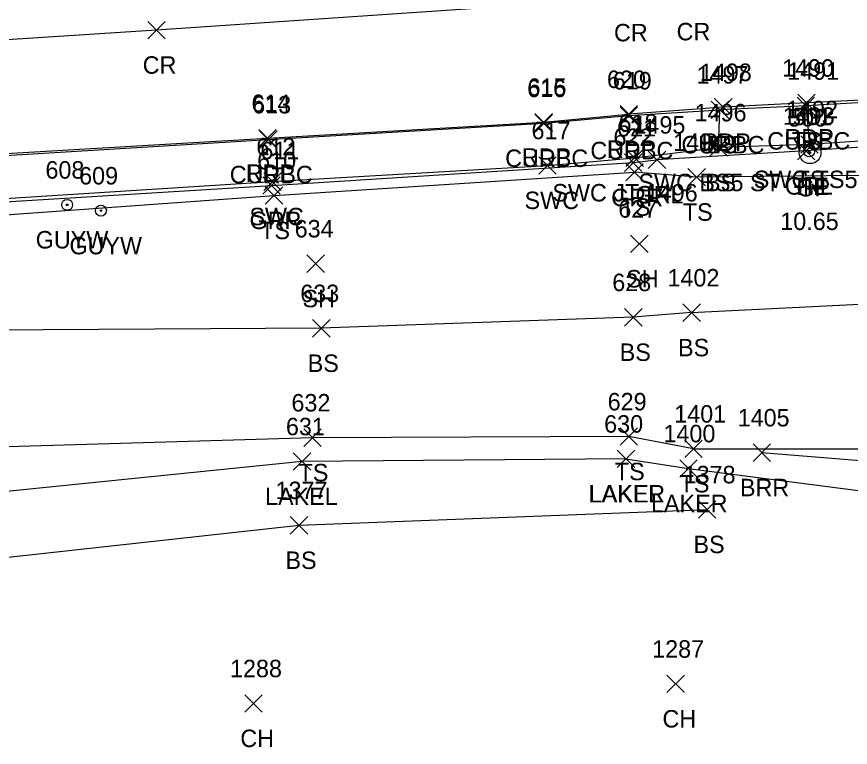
# Model space of a CAD drawing. Extents: x 1716490 to 1717645, y 888034 to 890004.
# Drawn here: x 1717358.9 to 1717454.4, y 888177 to 888260.7 of the extents above; entities that cross this region are included whole.
import ezdxf

# ---------------------------------------------------------------- set-up
doc = ezdxf.new("R2010")
doc.units = 0
for name, color, linetype in [('C_A', 7, 'Continuous'), ('C_C', 7, 'Continuous'), ('C_I', 7, 'Continuous'), ('CBP', 7, 'Continuous'), ('L_A', 7, 'Continuous'), ('L_I', 7, 'Continuous'), ('L_TIC', 7, 'Continuous'), ('LABL', 7, 'Continuous'), ('LAWE', 7, 'Continuous'), ('LELB', 7, 'Continuous'), ('P_A', 7, 'Continuous'), ('P_I', 7, 'Continuous'), ('P_TIC', 7, 'Continuous'), ('PET', 7, 'Continuous'), ('PRC', 7, 'Continuous'), ('R_A', 7, 'Continuous'), ('R_I', 7, 'Continuous'), ('R_TIC', 7, 'Continuous'), ('RC', 7, 'Continuous'), ('RGP', 7, 'Continuous'), ('RGR', 7, 'Continuous'), ('RSW', 7, 'Continuous'), ('U_A', 7, 'Continuous'), ('U_I', 7, 'Continuous'), ('UPGW', 7, 'Continuous')]:
    doc.layers.add(name, color=color, linetype=linetype)

msp = doc.modelspace()

# ---------------------------------------------------------------- linework, layer by layer
at = {"layer": 'CBP'}
for radius in [0.625, 0.0833]:
    msp.add_circle((1717449.723, 888245.268), radius, dxfattribs=at)
at = {"layer": 'L_TIC'}
for points in [[(1717448.343, 888249.478), (1717450.343, 888251.478)], [(1717450.343, 888249.478), (1717448.343, 888251.478)], [(1717438.503, 888249.043), (1717440.503, 888251.043)], [(1717440.503, 888249.043), (1717438.503, 888251.043)], [(1717438.35, 888244.712), (1717440.35, 888246.712)], [(1717440.35, 888244.712), (1717438.35, 888246.712)], [(1717448.774, 888245.071), (1717450.774, 888247.071)], [(1717450.774, 888245.071), (1717448.774, 888247.071)], [(1717428.711, 888241.895), (1717430.711, 888243.895)], [(1717430.711, 888241.895), (1717428.711, 888243.895)], [(1717435.838, 888241.33), (1717437.838, 888243.33)], [(1717437.838, 888241.33), (1717435.838, 888243.33)], [(1717387.412, 888239.225), (1717389.412, 888241.225)], [(1717389.412, 888239.225), (1717387.412, 888241.225)], [(1717429.269, 888233.684), (1717431.269, 888235.684)], [(1717431.269, 888233.684), (1717429.269, 888235.684)], [(1717392.184, 888231.418), (1717394.184, 888233.418)], [(1717394.184, 888231.418), (1717392.184, 888233.418)], [(1717435.262, 888225.802), (1717437.262, 888227.802)], [(1717437.262, 888225.802), (1717435.262, 888227.802)], [(1717428.575, 888225.271), (1717430.575, 888227.271)], [(1717430.575, 888225.271), (1717428.575, 888227.271)], [(1717392.828, 888224.01), (1717394.828, 888226.01)], [(1717394.828, 888224.01), (1717392.828, 888226.01)], [(1717391.814, 888211.48), (1717393.814, 888213.48)], [(1717393.814, 888211.48), (1717391.814, 888213.48)], [(1717428.056, 888211.605), (1717430.056, 888213.605)], [(1717430.056, 888211.605), (1717428.056, 888213.605)], [(1717435.472, 888210.206), (1717437.472, 888212.206)], [(1717437.472, 888210.206), (1717435.472, 888212.206)], [(1717443.304, 888209.768), (1717445.304, 888211.768)], [(1717445.304, 888209.768), (1717443.304, 888211.768)], [(1717390.617, 888208.758), (1717392.617, 888210.758)], [(1717392.617, 888208.758), (1717390.617, 888210.758)], [(1717427.732, 888209.055), (1717429.732, 888211.055)], [(1717429.732, 888209.055), (1717427.732, 888211.055)], [(1717427.732, 888209.055), (1717429.732, 888211.055)], [(1717429.732, 888209.055), (1717427.732, 888211.055)], [(1717434.889, 888207.946), (1717436.889, 888209.946)], [(1717436.889, 888207.946), (1717434.889, 888209.946)], [(1717434.889, 888207.946), (1717436.889, 888209.946)], [(1717436.889, 888207.946), (1717434.889, 888209.946)], [(1717437.033, 888203.252), (1717439.033, 888205.252)], [(1717439.033, 888203.252), (1717437.033, 888205.252)], [(1717390.277, 888201.442), (1717392.277, 888203.442)], [(1717392.277, 888201.442), (1717390.277, 888203.442)], [(1717433.429, 888183.275), (1717435.429, 888185.275)], [(1717435.429, 888183.275), (1717433.429, 888185.275)], [(1717385.06, 888181.038), (1717387.06, 888183.038)], [(1717387.06, 888181.038), (1717385.06, 888183.038)]]:
    msp.add_lwpolyline(points, dxfattribs=at)
at = {"layer": 'LABL'}
msp.add_lwpolyline([(1717444.304, 888210.768), (1717472.093, 888208.525), (1717508.027, 888209.443), (1717543.383, 888208.313), (1717559.79, 888208.697), (1717569.184, 888204.287)], dxfattribs=at)
at = {"layer": 'LAWE'}
for points in [[(1717428.732, 888210.055), (1717391.617, 888209.758), (1717351.712, 888205.712), (1717299.907, 888205.551), (1717265.677, 888204.481), (1717223.667, 888200.839), (1717208.555, 888201.757), (1717201.775, 888208.165), (1717191.379, 888215.041), (1717175.765, 888226.393)], [(1717428.732, 888210.055), (1717435.889, 888208.946)], [(1717435.889, 888208.946), (1717475.751, 888203.813), (1717512.343, 888207.141), (1717547.357, 888203.244), (1717562.879, 888195.852), (1717574.347, 888181.764)]]:
    msp.add_lwpolyline(points, dxfattribs=at)
at = {"layer": 'LELB'}
for points in [[(1717168.218, 888251.599), (1717169.763, 888223.631), (1717177.454, 888214.692), (1717194.469, 888204.087), (1717205.175, 888197.964), (1717222.801, 888195.904), (1717272.158, 888195.504), (1717301.802, 888198.153), (1717342.964, 888197.132), (1717391.277, 888202.442), (1717438.033, 888204.252)], [(1717449.343, 888250.478), (1717449.774, 888246.071)], [(1717439.35, 888245.712), (1717439.503, 888250.043)], [(1717558.191, 888231.225), (1717550.825, 888235.094), (1717537.711, 888239.81), (1717528.963, 888241.86), (1717509.305, 888244.845), (1717490.286, 888244.528), (1717470.299, 888242.67), (1717436.838, 888242.33)], [(1717195.004, 888228.651), (1717213.423, 888229.755), (1717254.51, 888232.617), (1717289.453, 888234.249), (1717344.856, 888237.074), (1717388.412, 888240.225), (1717429.711, 888242.895)], [(1717436.838, 888242.33), (1717429.711, 888242.895)], [(1717436.262, 888226.802), (1717464.721, 888228.238), (1717507.391, 888229.249), (1717536.749, 888229.804)], [(1717436.262, 888226.802), (1717429.575, 888226.271)], [(1717429.575, 888226.271), (1717393.828, 888225.01), (1717349.187, 888224.753), (1717340.986, 888224.942), (1717302.216, 888221.684), (1717265.436, 888218.579), (1717217.955, 888213.612)], [(1717436.472, 888211.206), (1717466.203, 888211.198), (1717507.829, 888212.694), (1717537.791, 888216.149), (1717563.771, 888215.069), (1717574.805, 888210.491), (1717582.49, 888199.54), (1717589.339, 888189.724)], [(1717429.056, 888212.605), (1717392.814, 888212.48), (1717352.659, 888211.275), (1717300.922, 888208.213), (1717265.266, 888207.117), (1717222.122, 888203.992)], [(1717436.472, 888211.206), (1717429.056, 888212.605)]]:
    msp.add_lwpolyline(points, dxfattribs=at)
at = {"layer": 'P_TIC'}
for points in [[(1717373.932, 888258.17), (1717375.932, 888260.17)], [(1717375.932, 888258.17), (1717373.932, 888260.17)], [(1717448.414, 888249.828), (1717450.414, 888251.828)], [(1717450.414, 888249.828), (1717448.414, 888251.828)], [(1717428.054, 888248.533), (1717430.054, 888250.533)], [(1717430.054, 888248.533), (1717428.054, 888250.533)], [(1717438.895, 888249.333), (1717440.895, 888251.333)], [(1717440.895, 888249.333), (1717438.895, 888251.333)], [(1717418.304, 888247.633), (1717420.304, 888249.633)], [(1717420.304, 888247.633), (1717418.304, 888249.633)], [(1717386.667, 888245.786), (1717388.667, 888247.786)], [(1717388.667, 888245.786), (1717386.667, 888247.786)]]:
    msp.add_lwpolyline(points, dxfattribs=at)
at = {"layer": 'PET'}
for points in [[(1717427.273, 888275.567), (1717374.238, 888271.922), (1717317.861, 888268.58), (1717269.995, 888265.537), (1717231.181, 888263.331), (1717177.059, 888260.693), (1717177.797, 888248.053), (1717178.6, 888236.513), (1717214.025, 888237.983), (1717254.522, 888239.738), (1717289.284, 888241.313), (1717339.424, 888243.96), (1717387.667, 888246.786), (1717419.304, 888248.633), (1717429.054, 888249.533)], [(1717594.517, 888190.334), (1717590.366, 888197.636), (1717582.375, 888209.703), (1717579.255, 888214.07), (1717576.4, 888218.115), (1717565.946, 888231.02), (1717560.234, 888236.413), (1717554.367, 888241.047), (1717546.423, 888245.577), (1717533.805, 888250.762), (1717523.466, 888253.269), (1717509.155, 888254.185), (1717488.825, 888253.07), (1717469.068, 888251.805), (1717449.414, 888250.828), (1717439.895, 888250.333)], [(1717439.895, 888250.333), (1717429.054, 888249.533)]]:
    msp.add_lwpolyline(points, dxfattribs=at)
at = {"layer": 'PRC'}
msp.add_lwpolyline([(1717428.93, 888262.876), (1717374.932, 888259.17), (1717318.782, 888255.519), (1717271.433, 888252.686), (1717231.272, 888251.088), (1717177.797, 888248.053)], dxfattribs=at)
at = {"layer": 'R_TIC'}
for points in [[(1717448.343, 888249.478), (1717450.343, 888251.478)], [(1717450.343, 888249.478), (1717448.343, 888251.478)], [(1717438.503, 888249.043), (1717440.503, 888251.043)], [(1717440.503, 888249.043), (1717438.503, 888251.043)], [(1717418.313, 888247.49), (1717420.313, 888249.49)], [(1717420.313, 888247.49), (1717418.313, 888249.49)], [(1717428.071, 888248.369), (1717430.071, 888250.369)], [(1717430.071, 888248.369), (1717428.071, 888250.369)], [(1717386.753, 888245.622), (1717388.753, 888247.622)], [(1717388.753, 888245.622), (1717386.753, 888247.622)], [(1717438.35, 888244.712), (1717440.35, 888246.712)], [(1717440.35, 888244.712), (1717438.35, 888246.712)], [(1717448.774, 888245.071), (1717450.774, 888247.071)], [(1717450.774, 888245.071), (1717448.774, 888247.071)], [(1717448.392, 888244.322), (1717450.392, 888246.322)], [(1717450.392, 888244.322), (1717448.392, 888246.322)], [(1717418.755, 888242.667), (1717420.755, 888244.667)], [(1717420.755, 888242.667), (1717418.755, 888244.667)], [(1717428.556, 888242.988), (1717430.556, 888244.988)], [(1717430.556, 888242.988), (1717428.556, 888244.988)], [(1717428.729, 888243.536), (1717430.729, 888245.536)], [(1717430.729, 888243.536), (1717428.729, 888245.536)], [(1717431.288, 888243.31), (1717433.288, 888245.31)], [(1717433.288, 888243.31), (1717431.288, 888245.31)], [(1717387.224, 888240.812), (1717389.224, 888242.812)], [(1717389.224, 888240.812), (1717387.224, 888242.812)], [(1717387.118, 888240.371), (1717389.118, 888242.371)], [(1717389.118, 888240.371), (1717387.118, 888242.371)]]:
    msp.add_lwpolyline(points, dxfattribs=at)
at = {"layer": 'RC'}
for points in [[(1717594.157, 888190.547), (1717590.511, 888197.229), (1717582.134, 888209.508), (1717579.157, 888213.908), (1717576.185, 888218.151), (1717565.853, 888230.61), (1717559.89, 888236.254), (1717554.327, 888240.707), (1717546.304, 888245.431), (1717533.609, 888250.562), (1717523.635, 888253.005), (1717509.034, 888253.878), (1717488.904, 888252.846), (1717469.137, 888251.622), (1717449.343, 888250.478), (1717439.503, 888250.043)], [(1717429.071, 888249.369), (1717439.503, 888250.043)], [(1717178.774, 888236.275), (1717214.142, 888237.798), (1717254.517, 888239.571), (1717289.15, 888241.078), (1717339.376, 888243.691), (1717387.753, 888246.622), (1717419.313, 888248.49), (1717429.071, 888249.369)]]:
    msp.add_lwpolyline(points, dxfattribs=at)
at = {"layer": 'RGP'}
msp.add_line((1717449.831, 888245.119), (1717449.831, 888245.119), dxfattribs=at)
for radius in [1.25, 0.0833]:
    msp.add_circle((1717449.831, 888245.119), radius, dxfattribs=at)
at = {"layer": 'RGR'}
for points in [[(1717550.825, 888235.094), (1717542.337, 888240.035), (1717527.82, 888245.616), (1717517.741, 888247.772), (1717508.577, 888248.408), (1717489.509, 888247.722), (1717469.569, 888246.675), (1717449.392, 888245.322), (1717432.288, 888244.31)], [(1717180.008, 888230.781), (1717185.315, 888230.201), (1717193.478, 888230.86), (1717213.849, 888231.841), (1717254.511, 888233.868), (1717289.664, 888235.619), (1717339.451, 888238.4), (1717388.118, 888241.371), (1717429.556, 888243.988)], [(1717429.556, 888243.988), (1717432.288, 888244.31)]]:
    msp.add_lwpolyline(points, dxfattribs=at)
at = {"layer": 'RSW'}
for points in [[(1717590.097, 888189.333), (1717586.586, 888194.982), (1717578.896, 888206.737), (1717575.658, 888211.348), (1717571.853, 888216.425), (1717562.584, 888227.864), (1717557.01, 888233.176), (1717551.758, 888236.948), (1717544.051, 888241.46), (1717532.127, 888246.38), (1717522.616, 888248.419), (1717508.753, 888249.365), (1717489.316, 888248.516), (1717469.398, 888247.378), (1717449.774, 888246.071), (1717439.35, 888245.712)], [(1717429.729, 888244.536), (1717439.35, 888245.712)], [(1717178.698, 888235.758), (1717178.897, 888231.459), (1717213.378, 888232.716), (1717254.439, 888234.734), (1717289.856, 888236.281), (1717339.502, 888238.742), (1717388.224, 888241.812), (1717419.755, 888243.667), (1717429.729, 888244.536)]]:
    msp.add_lwpolyline(points, dxfattribs=at)
at = {"layer": 'UPGW'}
for centre, radius in [((1717364.709, 888239.151), 0.625), ((1717364.709, 888239.151), 0.0833), ((1717368.574, 888238.486), 0.625), ((1717368.574, 888238.486), 0.0833)]:
    msp.add_circle(centre, radius, dxfattribs=at)

# ---------------------------------------------------------------- texts
at = {"layer": 'C_A'}
msp.add_text('TIE', height=2, dxfattribs=at).set_placement((1717447.802, 888240.268))
at = {"layer": 'C_C'}
msp.add_text('10.65', height=2, dxfattribs=at).set_placement((1717446.416, 888236.268))
at = {"layer": 'C_I'}
msp.add_text('501', height=2, dxfattribs=at).set_placement((1717447.849, 888248.268))
at = {"layer": 'L_A'}
for s, p in [('BS', (1717437.944, 888245.043)), ('TS', (1717447.752, 888245.478)), ('BS', (1717437.791, 888240.712)), ('TS', (1717448.183, 888241.071)), ('TS', (1717428.121, 888237.895)), ('TS', (1717435.248, 888237.33)), ('TS', (1717386.821, 888235.225)), ('SH', (1717428.757, 888229.684)), ('SH', (1717391.672, 888227.418)), ('BS', (1717434.703, 888221.802)), ('BS', (1717428.016, 888221.271)), ('BS', (1717392.269, 888220.01)), ('TS', (1717391.223, 888207.48)), ('TS', (1717427.465, 888207.605)), ('TS', (1717434.881, 888206.206)), ('BRR', (1717441.793, 888205.768)), ('LAKEL', (1717387.381, 888204.758)), ('LAKER', (1717424.44, 888205.055)), ('LAKEL', (1717424.495, 888205.055)), ('LAKER', (1717431.598, 888203.946)), ('LAKER', (1717431.598, 888203.946)), ('BS', (1717436.474, 888199.252)), ('BS', (1717389.718, 888197.442)), ('CH', (1717432.917, 888179.275)), ('CH', (1717384.548, 888177.038))]:
    msp.add_text(s, height=2, dxfattribs=at).set_placement(p)
at = {"layer": 'L_I'}
for s, p in [('1491', (1717447.217, 888253.478)), ('1497', (1717436.81, 888253.043)), ('1496', (1717436.602, 888248.712)), ('1492', (1717447.081, 888249.071)), ('622', (1717427.302, 888245.895)), ('1494', (1717434.145, 888245.33)), ('610', (1717386.483, 888243.225)), ('627', (1717427.859, 888237.684)), ('634', (1717390.774, 888235.418)), ('628', (1717427.166, 888229.271)), ('1402', (1717433.49, 888229.802)), ('633', (1717391.418, 888228.01)), ('632', (1717390.404, 888215.48)), ('629', (1717426.638, 888215.605)), ('1401', (1717434.267, 888214.206)), ('630', (1717426.236, 888213.055)), ('630', (1717426.236, 888213.055)), ('1405', (1717441.533, 888213.768)), ('631', (1717389.774, 888212.758)), ('1400', (1717433.031, 888211.946)), ('1400', (1717433.031, 888211.946)), ('1378', (1717435.34, 888207.252)), ('1377', (1717388.584, 888205.442)), ('1287', (1717431.736, 888187.275)), ('1288', (1717383.367, 888185.038))]:
    msp.add_text(s, height=2, dxfattribs=at).set_placement(p)
at = {"layer": 'P_A'}
for s, p in [('CR', (1717434.536, 888257.995)), ('CR', (1717427.363, 888257.876)), ('CR', (1717373.365, 888254.17)), ('RDP', (1717446.902, 888245.828)), ('RDP', (1717437.383, 888245.333)), ('RDP', (1717416.792, 888243.633)), ('RDP', (1717426.542, 888244.533)), ('RDP', (1717385.155, 888241.786))]:
    msp.add_text(s, height=2, dxfattribs=at).set_placement(p)
at = {"layer": 'P_I'}
for s, p in [('1498', (1717437.202, 888253.333)), ('1490', (1717446.635, 888253.828)), ('620', (1717426.557, 888252.533)), ('615', (1717417.461, 888251.633)), ('614', (1717385.824, 888249.786))]:
    msp.add_text(s, height=2, dxfattribs=at).set_placement(p)
at = {"layer": 'R_A'}
for s, p in [('CURBC', (1717435.086, 888245.043)), ('CURBC', (1717444.925, 888245.478)), ('CURBC', (1717424.654, 888244.369)), ('CURBC', (1717414.896, 888243.49)), ('CURBC', (1717383.336, 888241.622)), ('SWC BS5 ST', (1717430.161, 888240.712)), ('SWC TS5', (1717443.38, 888241.071)), ('GRL', (1717446.936, 888240.322)), ('GP', (1717448.264, 888240.119)), ('SWC JT 1496', (1717420.304, 888239.536)), ('GRR', (1717427.044, 888238.988)), ('GRL', (1717429.831, 888239.31)), ('SWC', (1717417.117, 888238.667)), ('SWC', (1717385.587, 888236.812)), ('GRR', (1717385.606, 888236.371))]:
    msp.add_text(s, height=2, dxfattribs=at).set_placement(p)
at = {"layer": 'R_I'}
for s, p in [('1491', (1717447.217, 888253.478)), ('619', (1717427.221, 888252.369)), ('1497', (1717436.81, 888253.043)), ('616', (1717417.416, 888251.49)), ('613', (1717385.91, 888249.622)), ('1496', (1717436.602, 888248.712)), ('1492', (1717447.081, 888249.071)), ('618', (1717427.887, 888247.536)), ('1493', (1717446.699, 888248.322)), ('500', (1717447.304, 888248.119)), ('617', (1717417.912, 888246.667)), ('621', (1717427.713, 888246.988)), ('1495', (1717429.595, 888247.31)), ('612', (1717386.382, 888244.812)), ('611', (1717386.843, 888244.371))]:
    msp.add_text(s, height=2, dxfattribs=at).set_placement(p)
at = {"layer": 'U_A'}
for p in [(1717361.103, 888234.151), (1717364.968, 888233.486)]:
    msp.add_text('GUYW', height=2, dxfattribs=at).set_placement(p)
at = {"layer": 'U_I'}
for s, p in [('608', (1717362.221, 888242.151)), ('609', (1717366.078, 888241.486))]:
    msp.add_text(s, height=2, dxfattribs=at).set_placement(p)

doc.saveas('drawing.dxf')
